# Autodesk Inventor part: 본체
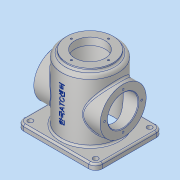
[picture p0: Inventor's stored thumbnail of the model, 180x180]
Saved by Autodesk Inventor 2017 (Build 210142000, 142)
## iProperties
Part Number: 본체
Material: 알루미늄 6061
Document SubType Name: Modeling
Designer: MRC
Mass: 1234.41 g
Surface Area: 1072.02 cm^2
Volume: 457.188 cm^3
Density: 2.7 g/cm^3
Appearance: 알루미늄 - 평지
Author: MRC
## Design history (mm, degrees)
sketch "스케치1"
  geometry: C1 r 50 at (0, 0); 1 further point
  constraints: 1 centre point, 1 coincident
  dimensions: "d0" = 100 diameter of C1
extrude "돌출1" new body sketch "스케치1" stored distance "d1" = 120; taper "d2" = 0 deg
sketch "스케치3"
  geometry: C1 r 41 at (0, 0); 1 further point
  constraints: 1 centre point, 1 coincident
  dimensions: "d7" = 82 diameter of C1
extrude "돌출3" join sketch "스케치3" stored distance "d8" = 118; taper "d9" = 0 deg
sketch "스케치4"
  geometry: C1 r 27 at (0, 0); 1 further point
  constraints: 1 centre point, 1 coincident
  dimensions: "d10" = 54 diameter of C1
extrude "돌출4" cut sketch "스케치4" stored distance "d11" = 118; taper "d12" = 0 deg
sketch "스케치5"
  geometry: L1 (-70, -60)-(70, -60); L2 (70, -60)-(70, 60); L3 (70, 60)-(-70, 60); L4 (-70, 60)-(-70, -60); L5 (-70, -60)-(70, 60); L6 (70, -60)-(-70, 60); C1 r 50 at (0, 0) reference
  constraints: 12 end point, 2 midpoint, 2 parallel, 1 horizontal, 1 perpendicular
  dimensions: "d13" = 140 distance of L3.end L2.end; "d14" = 120 distance of L2.end L1.end
extrude "돌출5" join sketch "스케치5" distance "d15" = 10; taper "d16" = 0 deg
fillet "모깎기1" dims "d26" = 6
fillet "모깎기4" dims "d29" = 3
fillet "모깎기6" dims "d31" = 12
chamfer "모따기2" distance "d36" = 1; stored, may be unused: second distance "d37" = 2, angle "d38" = 45 deg
sketch "스케치10"
  geometry: C1 r 41 at (0, 0) reference; 4 further points
  constraints: 1 vertical alignment, 5 other
  dimensions: "d46" = 33 distance of C1.centre point (0, 33); "d49" = 360 deg dimension on C1.centre point (0, 33) (derived)
hole "구멍2" sketch "스케치10" at (0, 33), (-33, 0), (0, -33), (33, 0) diameter "d51" = 3.242; stored, may be unused: countersink angle "d55" = 90 deg, drill point angle "d57" = 118 deg; dims "d52" = 8, "d53" = 4, "d54" = 2, "d56" = 10
node "작업 평면1"
sketch "스케치12"
  geometry: L1 (58, -60)-(-58, -60) reference; 6 further points; 1 other entity
  constraints: 1 vertical alignment, 2 other
  dimensions: "d90" = 66 distance from line of L1 point (0, 6)
feature "엠보싱1" sketch "스케치12" dims "d72" = 0.5, "d73" = 0
sketch "스케치16"
  geometry: C1 r 42 at (0, 0); 1 further point
  constraints: 1 centre point, 1 coincident
  dimensions: "d77" = 84 diameter of C1
extrude "돌출10" cut sketch "스케치16" distance "d78" = 112; taper "d79" = 0 deg
sketch "스케치17"
  geometry: C1 r 44 at (0, 0) reference; C2 r 41 at (0, 0)
  constraints: 1 centre point, 1 coincident
  dimensions: "d80" = 82 diameter of C2
extrude "돌출11" join sketch "스케치17" distance "d81" = 5; taper "d82" = 0 deg
sketch "스케치18"
  geometry: C1 r 42 at (0, 0) reference; C2 r 27 at (0, 0)
  constraints: 1 centre point, 1 coincident
  dimensions: "d83" = 54 diameter of C2
extrude "돌출12" cut sketch "스케치18" stored distance "d84" = 5; taper "d85" = 0 deg
fillet "모깎기8" dims "d86" = 3
sketch "스케치19"
  geometry: C1 r 4.5 at (58, 48); A1 r 9 centre (58, 48) between (67, 48) and (58, 57) reference
  constraints: 1 centre point, 1 coincident
  dimensions: "d87" = 9 diameter of C1
extrude "돌출13" cut sketch "스케치19" stored distance "d88" = 5; taper "d89" = 0 deg
sketch "스케치20"
  geometry: C1 r 27 at (0, 0) reference; C2 r 41 at (0, 0) reference; 4 further points
  constraints: 1 vertical alignment, 5 other
  dimensions: "d91" = 33 distance of C1.centre point (0, 33); "d94" = 360 deg dimension on C2.centre point (0, 33) (derived)
hole "구멍4" sketch "스케치20" at (0, 33), (-33, 0), (0, -33), (33, 0) diameter "d96" = 3.242; stored, may be unused: countersink angle "d100" = 90 deg, drill point angle "d102" = 118 deg; dims "d97" = 8, "d98" = 4, "d99" = 2, "d101" = 10
node "솔리드1"
mirror "미러1"
mirror "미러2"
mirror "미러3"
